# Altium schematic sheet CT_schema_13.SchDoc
size 389 x 385 mm
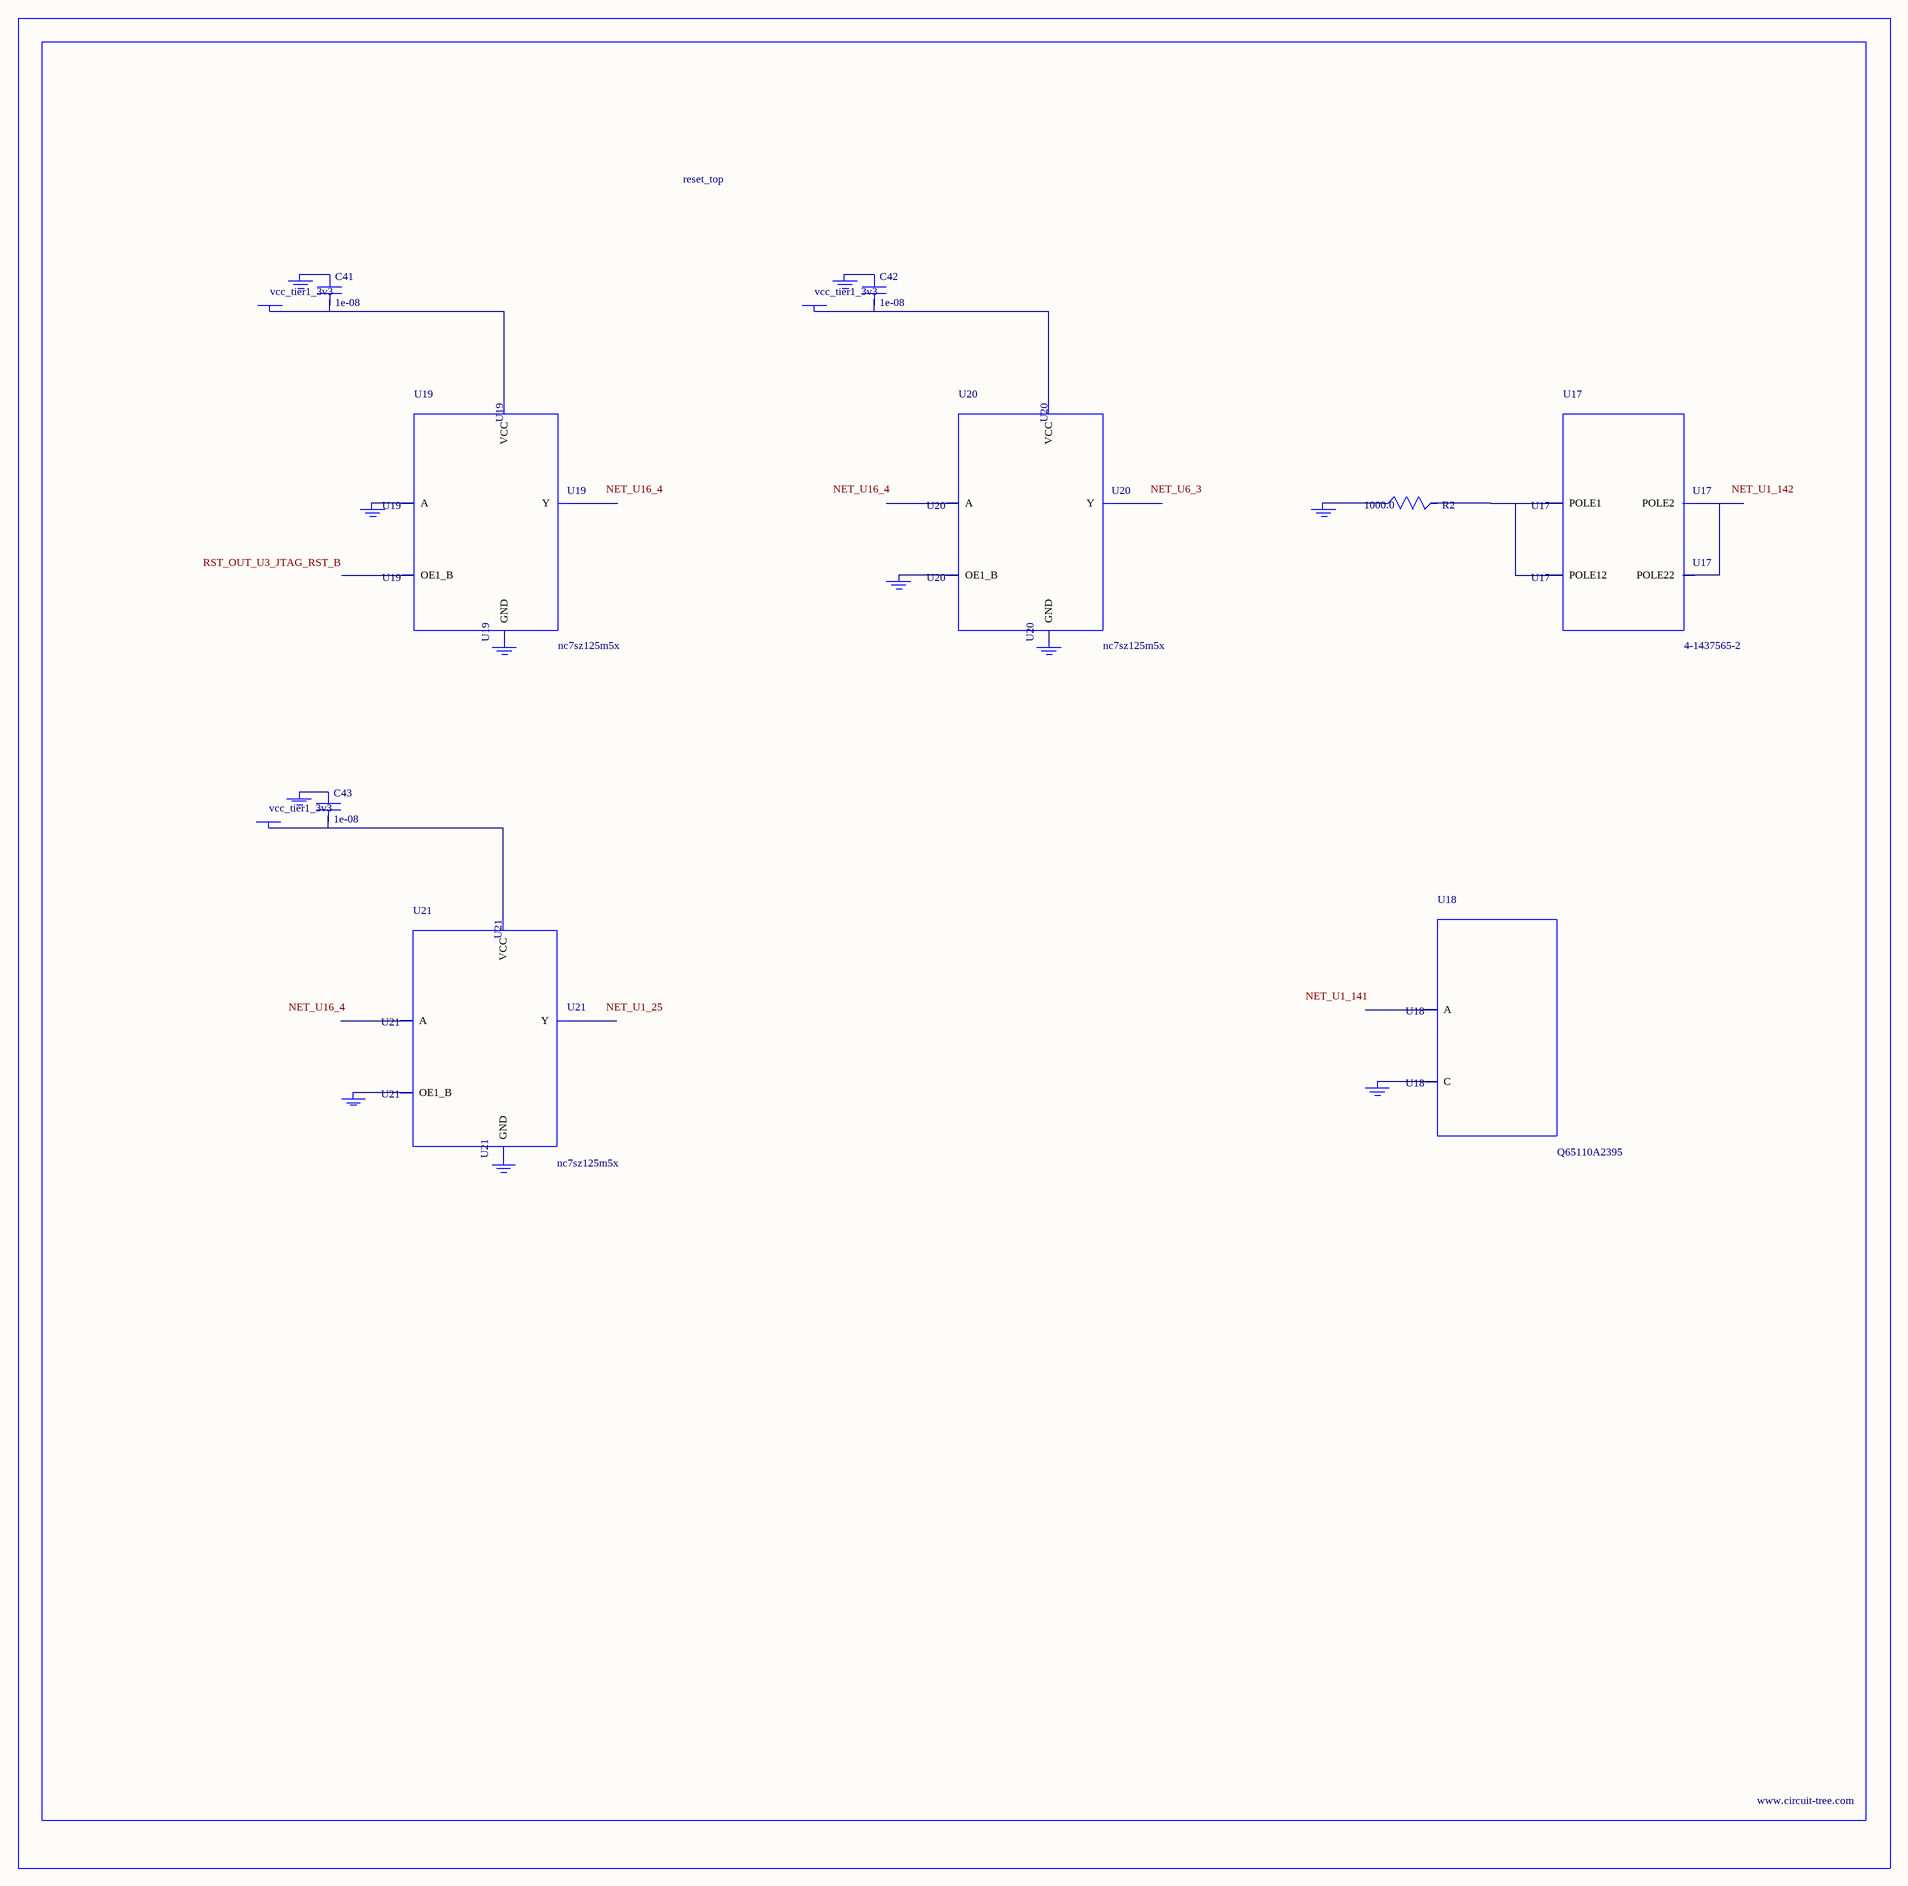
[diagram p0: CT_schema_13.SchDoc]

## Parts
BORDER12  (no value)
C41  1e-08  [C0402]
C42  1e-08  [C0402]
C43  1e-08  [C0402]
GND_INSTANCE_12_0  (no value)
GND_INSTANCE_12_1  (no value)
GND_INSTANCE_12_2  (no value)
GND_INSTANCE_12_3  (no value)
GND_INSTANCE_12_4  (no value)
GND_INSTANCE_12_5  (no value)
GND_INSTANCE_12_6  (no value)
GND_INSTANCE_12_7  (no value)
GND_INSTANCE_12_8  (no value)
GND_INSTANCE_12_9  (no value)
GND_INSTANCE_12_10  (no value)
POWER_INSTANCE_12_0  vcc_tier1_3v3
POWER_INSTANCE_12_1  vcc_tier1_3v3
POWER_INSTANCE_12_2  vcc_tier1_3v3
R2  1000.0  [R0603]
U17  4-1437565-2  [SW_4-1437565-2]
U18  Q65110A2395  [LGM67K-G1J2-24-Z]
U19  nc7sz125m5x  [NC7SZ125M5X]
U20  nc7sz125m5x  [NC7SZ125M5X]
U21  nc7sz125m5x  [NC7SZ125M5X]

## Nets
NetC41_1: C41.1 GND_INSTANCE_12_2.0(GND)
NetC41_2: C41.2 POWER_INSTANCE_12_0.0(PWR) U19.5(VCC)
NetC42_1: C42.1 GND_INSTANCE_12_5.0(GND)
NetC42_2: C42.2 POWER_INSTANCE_12_1.0(PWR) U20.5(VCC)
NetC43_1: C43.1 GND_INSTANCE_12_8.0(GND)
NetC43_2: C43.2 POWER_INSTANCE_12_2.0(PWR) U21.5(VCC)
NetGND_INSTANCE_12_0_0: GND_INSTANCE_12_0.0(GND) R2.1
NetGND_INSTANCE_12_1_0: GND_INSTANCE_12_1.0(GND) U18.C
NetGND_INSTANCE_12_3_0: GND_INSTANCE_12_3.0(GND) U19.2(A)
NetGND_INSTANCE_12_4_0: GND_INSTANCE_12_4.0(GND) U19.3(GND)
NetGND_INSTANCE_12_6_0: GND_INSTANCE_12_6.0(GND) U20.1(OE1_B)
NetGND_INSTANCE_12_7_0: GND_INSTANCE_12_7.0(GND) U20.3(GND)
NetGND_INSTANCE_12_9_0: GND_INSTANCE_12_9.0(GND) U21.1(OE1_B)
NetGND_INSTANCE_12_10_0: GND_INSTANCE_12_10.0(GND) U21.3(GND)
NetR2_2: R2.2 U17.1(POLE1) U17.2(POLE12)
NetU17_3: U17.3(POLE2) U17.4(POLE22)

Not connected (* = marked no-connect by the designer): U18 A; U19 1(OE1_B) 4(Y); U20 2(A) 4(Y); U21 2(A) 4(Y)

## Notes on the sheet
- Labels drawn without touching a wire or pin: NET_U1_25, NET_U1_141, NET_U1_142, NET_U6_3, NET_U16_4, RST_OUT_U3_JTAG_RST_B

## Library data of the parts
BORDER12 = BORDER_PAGE12
C41-C43 = C0402C103K3RAC
GND_INSTANCE_12_0-GND_INSTANCE_12_10 = GND
POWER_INSTANCE_12_0-POWER_INSTANCE_12_2 = PWR
R2 = RC0603JR-071KL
